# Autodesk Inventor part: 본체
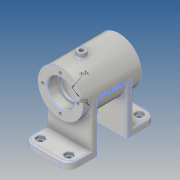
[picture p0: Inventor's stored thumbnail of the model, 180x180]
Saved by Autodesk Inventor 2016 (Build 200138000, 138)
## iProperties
Created: 2017-02
Part Number: 본체
Material: 알루미늄 6061
Document SubType Name: Modeling
Designer: Administrator
Density: 2.7 g/cm^3
Appearance: 알루미늄 - 평지
Mass: 352.335 g
Surface Area: 424.625 cm^2
Volume: 130.495 cm^3
Author: Administrator
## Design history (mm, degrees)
sketch "스케치11"
  geometry: C1 r 27 at (0, 0); 1 further point
  constraints: 1 centre point, 1 coincident
  dimensions: "d33" = 54 diameter of C1
extrude "돌출6" new body sketch "스케치11" stored distance "d34" = 70; taper "d35" = 0 deg
sketch "스케치12"
  geometry: L1 (0, 40.426)-(0, -63.338); L2 (27, 35)-(-27, 35) reference; L3 (27, -35)-(27, 35) reference; L4 (16, 35)-(16, 23); L5 (16, 23)-(14, 23); L6 (14, 23)-(14, 20); L7 (14, 20)-(22, 20); L8 (22, 20)-(22, -20); L9 (22, -20)-(14, -20); L10 (14, -20)-(14, -23); L11 (14, -23)-(16, -23); L12 (16, -23)-(16, -35); L13 (-27, -35)-(27, -35) reference; L14 (16, 35)-(0, 35); L15 (16, -35)-(0, -35); L16 (0, 35)-(0, -35); 2 further points
  constraints: 26 end point, 8 perpendicular, 3 midpoint, 3 point on line, 2 vertical, 1 collinear, 1 horizontal alignment
  dimensions: "d36" = 12 distance of L4.start L4.end; "d37" = 12 distance of L11.end L12.end; "d38" = 40 distance of L7.end L8.end; "d39" = 32 diameter of L4 L1; "d40" = 28 diameter of L6 L1; "d41" = 28 diameter of L10 L1; "d42" = 32 diameter of L12 L1; "d43" = 44 diameter of L8 L1
revolve "회전2" sketch "스케치12" stored, may be unused: angle "d44" = 90 deg
sketch "스케치13"
  geometry: L1 (0, 0)-(0, -32.817); L2 (0, 0)-(-16.339, -25.16); 1 further point
  constraints: 4 end point, 1 vertical
  dimensions: "d133" = 33 deg angle of L2 L1; "d134" = 30 distance of L1.start L2.end
node "작업 평면5"
sketch "스케치15"
  geometry: L1 (27, -52)-(-27, -52); L2 (-27, -52)-(-27, 52); L3 (-27, 52)-(27, 52); L4 (27, 52)-(27, -52); 3 further points
  constraints: 8 end point, 2 midpoint, 2 parallel, 1 horizontal, 1 horizontal alignment, 1 perpendicular, 1 vertical alignment
  dimensions: "d51" = 54 distance of L1.start L1.end; "d52" = 104 distance of L3.end L1.start
extrude "돌출8" join sketch "스케치15" distance "d53" = 8; taper "d54" = 0 deg
sketch "스케치16"
  geometry: L1 (27, -17)-(-27, -17); L2 (-27, -17)-(-27, 17); L3 (-27, 17)-(27, 17); L4 (27, 17)-(27, -17); 3 further points
  constraints: 8 end point, 2 midpoint, 2 parallel, 1 horizontal, 1 horizontal alignment, 1 perpendicular, 1 vertical alignment
  dimensions: "d55" = 34 distance of L1.end L2.end; "d56" = 54 distance of L1.start L1.end
extrude "돌출9" cut sketch "스케치16" distance "d57" = 8; taper "d58" = 0 deg
sketch "스케치17"
  geometry: L1 (27, -17)-(-27, -17) reference; L2 (27, -52)-(27, -17) reference; L3 (-27, -17)-(27, -17); L4 (27, -17)-(27, -25); L5 (27, -25)-(-27, -25); L6 (-27, -25)-(-27, -17); 1 further point
  constraints: 8 end point, 2 parallel, 1 horizontal, 1 perpendicular, 1 point on line
  dimensions: "d59" = 8 distance between parallel lines of L1 L5
extrude "돌출10" join sketch "스케치17" stored distance "d60" = 8; taper "d61" = 0 deg
node "작업 평면6"
sketch "스케치18"
  geometry: L1 (27, 35)-(-27, 35) reference; C1 r 5 at (0, 10); 1 further point
  constraints: 1 centre point, 1 vertical alignment
  dimensions: "d63" = 10 diameter of C1; "d64" = 25 distance from line of L1 C1.centre
extrude "돌출11" join sketch "스케치18" stored distance "d65" = 8; taper "d66" = 0 deg
sketch "스케치19" dims "d67" = 9
  geometry: L1 (-27, -52)-(27, -52) reference; L2 (27, -52)-(27, -25) reference; L3 (12.5, -39.402)-(17, -36.804); L4 (17, -36.804)-(21.5, -39.402); L5 (21.5, -39.402)-(21.5, -44.598); L6 (21.5, -44.598)-(17, -47.196); L7 (17, -47.196)-(12.5, -44.598); L8 (12.5, -44.598)-(12.5, -39.402); 5 further points
  constraints: 12 end point, 2 horizontal alignment, 2 midpoint, 1 coincident, 15 other
  dimensions: "d68" = 10 distance from line of L1 point (17, -42); "d69" = 10 distance from line of L2 point (17, -42)
extrude "돌출12" cut sketch "스케치19" distance "d70" = 3; taper "d71" = 0 deg
sketch "스케치20"
  geometry: L1 (21.5, -39.402)-(21.5, -44.598) reference; 4 further points
  constraints: 1 horizontal alignment, 1 midpoint, 1 vertical alignment
hole "구멍1" sketch "스케치20" at (17, -42) diameter "d72" = 5; stored, may be unused: countersink angle "d76" = 90 deg, drill point angle "d78" = 118 deg; dims "d73" = 6, "d74" = 4, "d75" = 2, "d77" = 8
node "작업 평면7"
sketch "스케치21"
  geometry: L1 (2.402, 16.034)-(2.402, -16.034); L2 (2.402, -16.034)-(-2.402, -16.034); L3 (-2.402, -16.034)-(-2.402, 16.034); L4 (-2.402, 16.034)-(2.402, 16.034); L5 (-2.402, -16.034)-(2.402, 16.034); L6 (-2.402, 16.034)-(2.402, -16.034); L7 (27, 35)-(-27, 35) reference; 2 further points
  constraints: 4 end point, 1 coincident, 1 midpoint, 2 other
  dimensions: "d80" = 27 horizontal distance of L7.start point (0, 0)
feature "엠보싱1" sketch "스케치21" dims "d33" = 54, "d36" = 12, "d37" = 12, "d38" = 40, "d39" = 32, "d40" = 28, "d41" = 28, "d42" = 32, "d43" = 44, "d81" = 0.5, "d82" = 0
fillet "모깎기1" dims "d83" = 10
fillet "모깎기2" dims "d84" = 2
fillet "모깎기4" dims "d86" = 2
fillet "모깎기5" dims "d87" = 2
chamfer "모따기1" distance "d88" = 1; stored, may be unused: second distance "d89" = 2, angle "d90" = 45 deg
hole "구멍2" diameter "d93" = 5.188; stored, may be unused: countersink angle "d97" = 90 deg, drill point angle "d99" = 0 deg; dims "d91" = 10, "d92" = 10, "d94" = 12, "d95" = 4, "d96" = 2, "d98" = 16
sketch "스케치22" dims "d109" = 42
  geometry: C1 r 27 at (0, 0) reference; C2 r 17 at (0, 0) reference; 2 further points
  constraints: 2 vertical alignment, 1 coincident, 2 other
hole "구멍4" sketch "스케치22" at (0, 21) diameter "d110" = 3.242; stored, may be unused: countersink angle "d114" = 90 deg, drill point angle "d116" = 118 deg; dims "d111" = 8, "d112" = 4, "d113" = 2, "d115" = 10
sketch "스케치23" dims "d120" = 42
  geometry: C1 r 27 at (0, 0) reference; C2 r 17 at (0, 0) reference; 2 further points
  constraints: 2 vertical alignment, 1 coincident, 2 other
hole "구멍5" sketch "스케치23" at (0, 21) diameter "d121" = 3.242; stored, may be unused: countersink angle "d125" = 90 deg, drill point angle "d127" = 118 deg; dims "d122" = 8, "d123" = 4, "d124" = 2, "d126" = 10
fillet "모깎기6" dims "d131" = 2
node "작업 평면8"
sketch "스케치25"
  geometry: C1 r 6 at (0, 0); 1 further point
  constraints: 1 centre point, 1 coincident
  dimensions: "d135" = 12 diameter of C1
extrude "돌출13" join sketch "스케치25" stored distance "d136" = 3; taper "d137" = 0 deg
fillet "모깎기8" dims "d138" = 2
hole "구멍6" diameter "d141" = 5.188; stored, may be unused: countersink angle "d145" = 90 deg, drill point angle "d147" = 118 deg; dims "d139" = 10, "d140" = 10, "d142" = 12, "d143" = 4, "d144" = 2, "d146" = 16
fillet "모깎기9" dims "d148" = 3
node "솔리드2"
mirror "대칭1"
mirror "대칭2"
mirror "대칭3"
pattern_circular "원형 패턴1" dims angle "d118" = 360 deg
pattern_circular "원형 패턴2" dims angle "d129" = 360 deg
other parameters: "d62" = -92, "d79" = 30.1625
